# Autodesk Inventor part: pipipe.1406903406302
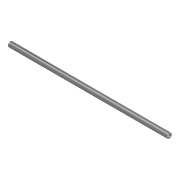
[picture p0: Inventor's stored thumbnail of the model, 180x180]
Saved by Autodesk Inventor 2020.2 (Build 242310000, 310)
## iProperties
Manager: www.cadconsulting.pl
Company: Fabian Stasiak CAD Consulting
IsCustomPart: 1
NAME: PIPING: JIS G 3458 Pipe
DATA: <meta><inlinegroups number="1" deflen="10"></inlinegroups><connections number="2"></connections><angles><a>3.14159265358979</a></angles></meta>
Created: 2014-08
Material: Stal, stopowa
Description: Rura
Document SubType Name: Modeling
Standard: JIS G 3458
Designer: F.Stasiak
Standards Organization: JIS
Language: pl-PL
Size Designation: 40 A x Sch 80 - 100
Categories: <MemberInstance><Categories><Category DisplayName="Rury cienko- i grubościenne" InternalName="4347fa0f-2144-441d-94cd-e3e15c92b736" Mnemonic="TUBEANDPIPE"><Cate
Stock Number: JIS G 3458 Rura 40 A x Sch 80
Density: 7.73 g/cm^3
Appearance: Częściowo polerowana
Catalog Web Link: www.expertbooks.pl
L: 1536,000 mm
PL: 1536,000 mm
Author: F.Stasiak
Subject: Zbiór ćwiczeń. Autodesk Inventor 2020. Kurs Professional
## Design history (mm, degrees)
sketch "Sketch1"
  geometry: C1 r 24.3 at (0, 0); C2 r 19.2 at (0, 0); 1 further point
  constraints: 2 centre point, 2 coincident, 1 concentric
  dimensions: "d0" = 48.6 diameter of C1 (= OD); "d1" = 38.4 diameter of C2 (= OD - 2 x t)
extrude "Extrusion1" new body sketch "Sketch1" distance "d2" = 1536 (= L); taper "d3" = 0 deg
workaxis "Work Axis1"
workpoint "Work Point1"
workaxis "Work Axis2"
workpoint "Work Point2"
body "Solid1"
other parameters: "OD" = 48.6 [user parameter; used in 2 equation terms], "t" = 5.1 [user parameter; used in 1 equation term], "L" = 1536 (= PL) [user parameter; used in 1 equation term], "ID" = 38.4 [user parameter], "PL" = 1536 [user parameter; used in 1 equation term], "Size_Designation" = 12.345 [user parameter]
